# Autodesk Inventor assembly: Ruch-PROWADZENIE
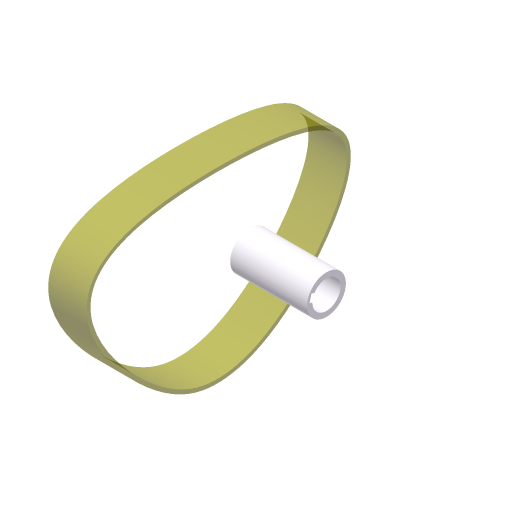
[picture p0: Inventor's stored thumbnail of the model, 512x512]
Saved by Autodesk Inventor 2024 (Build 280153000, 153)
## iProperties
Created: 2023-03
Part Number: Ruch-PROWADZENIE
Document SubType Name: Assembly
Designer: Andrzej Jaskulski
Manufacturer: Standard
Standards Organization: Custom
Stock Number: Ruch-PROWADZENIE
Checked By: A.J.
Engr Approved By: Andrzej Jaskulski
Mfg Approved By: Andrzej Jaskulski
Authority: A.J.
Company: ATC
Title: A.J.: Kurs R2024-MEP
Author: Andrzej Jaskulski
Revision Number: 1/24
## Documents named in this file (3)
- C:\Users\AndJas\Documents\R2024-MEP\Obszar roboczy\Ruch-PROWADZENIE.iam
- C:\Users\AndJas\Documents\R2024-MEP\Obszar roboczy\Ruch-PROWADZENIE-Listwa.ipt
- C:\Users\AndJas\Documents\R2024-MEP\Obszar roboczy\Ruch-PROWADZENIE-Rolka.ipt
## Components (2 placed, 2 different names)
1. Ruch-PROWADZENIE-Listwa:1 — PROWADZENIE, Równoległość-CZÓŁ
2. Ruch-PROWADZENIE-Rolka:1 — PROWADZENIE, Równoległość-CZÓŁ
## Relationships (2: Transitional 1, Flush 1)
- PROWADZENIE [Transitional]: Ruch-PROWADZENIE-Listwa:1 ↔ Ruch-PROWADZENIE-Rolka:1
- Równoległość-CZÓŁ [Flush]: Ruch-PROWADZENIE-Listwa:1 ↔ Ruch-PROWADZENIE-Rolka:1
## Named parameters: OBWÓD = 94.2 mm
